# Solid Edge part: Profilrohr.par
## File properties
Username: ahadarics
Dokumentum tartalom típus: 0
Author: ahadarics
Last saved by: ahadarics
Revision: 77
Sűrűség: 0,000 kg/m^3
Pontosság: 0,990
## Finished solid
Body 1: solid body, 6 faces, 6 edges, 0 vertices.
  Faces by surface: cone 2, cylinder 2, plane 2
  Edges by curve: circle 6
Bounding box of the edges (mm): 17.270 x 17.270 x 57.000, from (-8.635, -8.635, -36) to (8.635, 8.635, 21).
Cylindrical faces by radius (mm): R8 x1, R8.635 x1
Conical faces (half-angle, radius in mm at the cone's reference point): 15 deg R8.067 x2
Planar faces by outward normal: +z 1, -z 1
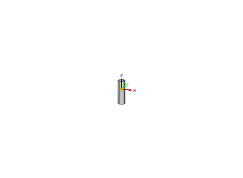
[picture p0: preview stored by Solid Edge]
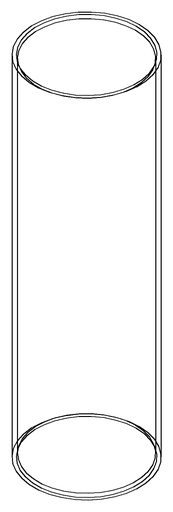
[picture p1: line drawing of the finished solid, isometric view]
